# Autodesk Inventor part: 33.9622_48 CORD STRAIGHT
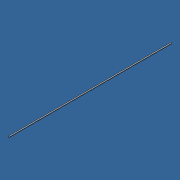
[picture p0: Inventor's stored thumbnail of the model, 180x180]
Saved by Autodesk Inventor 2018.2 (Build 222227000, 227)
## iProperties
Created: 2018-05
Part Number: 33.9622_48 CORD STRAIGHT
Material: Generic
Document SubType Name: Modeling
Designer: amoles
Density: 1 g/cm^3
Appearance: White
Author: amoles
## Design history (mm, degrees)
sketch "Sketch1"
  geometry: L1 (-3.5, 1.65)-(3.5, 1.65); L2 (3.5, 1.65)-(3.5, -1.65); L3 (3.5, -1.65)-(-3.5, -1.65); L4 (-3.5, -1.65)-(-3.5, 1.65); 3 further points
  constraints: 8 end point, 2 midpoint, 2 parallel, 1 horizontal, 1 horizontal alignment, 1 perpendicular, 1 vertical alignment
  dimensions: "d0" = 7 distance of L1.start L1.end; "d1" = 3.3 distance of L1.end L2.end
extrude "Extrusion1" new body sketch "Sketch1" distance "d2" = 1104.9; taper "d3" = 0 deg
body "Solid1"
